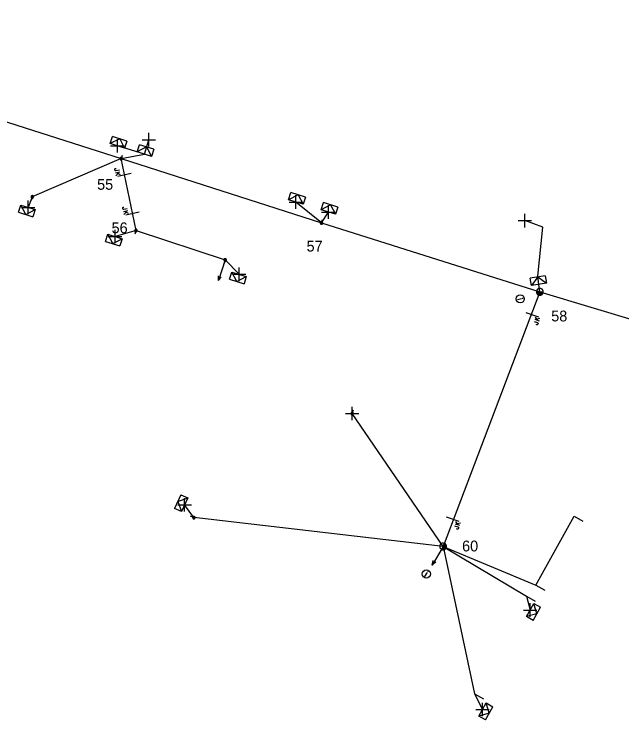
# Model space of a CAD drawing. Extents: x -540247 to -537390, y -1183887 to -1180355.
# Drawn here: x -537663.5 to -537607.2, y -1180540.3 to -1180475 of the extents above; entities that cross this region are included whole.
import ezdxf

# ---------------------------------------------------------------- set-up
doc = ezdxf.new("R2010")
doc.units = 0
for name, color, linetype in [('Vrstva 1', 7, 'Continuous'), ('Vrstva 10', 7, 'Continuous'), ('Vrstva 13', 7, 'Continuous'), ('Vrstva 14', 7, 'Continuous'), ('Vrstva 15', 7, 'Continuous'), ('Vrstva 18', 7, 'Continuous'), ('Vrstva 2', 7, 'Continuous'), ('Vrstva 31', 7, 'Continuous'), ('Vrstva 34', 7, 'Continuous'), ('Vrstva 36', 7, 'Continuous'), ('Vrstva 4', 7, 'Continuous'), ('Vrstva 50', 7, 'Continuous'), ('Vrstva 52', 7, 'Continuous'), ('Vrstva 54', 7, 'Continuous'), ('Vrstva 8', 7, 'Continuous'), ('Vrstva 9', 7, 'Continuous')]:
    doc.layers.add(name, color=color, linetype=linetype)

# ---------------------------------------------------------------- blocks, each defined once
blk = doc.blocks.new('NN440')
at = {"layer": 'Vrstva 2'}
for points in [[(0.63, 0), (0.63, 0.06), (0.62, 0.13), (0.6, 0.19), (0.58, 0.25), (0.55, 0.31), (0.51, 0.37), (0.47, 0.42), (0.42, 0.46), (0.37, 0.51), (0.32, 0.54), (0.26, 0.57), (0.2, 0.59), (0.13, 0.61), (0.07, 0.62), (0, 0.63), (-0.06, 0.62), (-0.13, 0.61), (-0.19, 0.59), (-0.26, 0.57), (-0.31, 0.54), (-0.37, 0.51), (-0.42, 0.46), (-0.47, 0.42), (-0.51, 0.37), (-0.54, 0.31), (-0.57, 0.25), (-0.6, 0.19), (-0.62, 0.13), (-0.63, 0.06), (-0.63, 0), (-0.63, -0.07), (-0.62, -0.14), (-0.6, -0.2), (-0.57, -0.26), (-0.54, -0.32), (-0.51, -0.37), (-0.47, -0.43), (-0.42, -0.47), (-0.37, -0.51), (-0.31, -0.55), (-0.26, -0.58), (-0.19, -0.6), (-0.13, -0.62), (-0.06, -0.63), (0, -0.63), (0.07, -0.63), (0.13, -0.62), (0.2, -0.6), (0.26, -0.58), (0.32, -0.55), (0.37, -0.51), (0.42, -0.47), (0.47, -0.43), (0.51, -0.37), (0.55, -0.32), (0.58, -0.26), (0.6, -0.2), (0.62, -0.14), (0.63, -0.07), (0.63, 0)], [(-0.63, 0), (0.63, 0)], [(-0.6, -0.18), (0.57, -0.18)], [(-0.51, -0.32), (0.5, -0.32)], [(-0.37, -0.47), (0.35, -0.47)]]:
    blk.add_lwpolyline(points, dxfattribs=at)
blk = doc.blocks.new('NN560')
at = {"layer": 'Vrstva 2'}
for points in [[(1.999, -0.001), (1.59, 0.141)], [(0, -0.001), (1.999, -0.001)], [(1.999, -0.001), (1.59, -0.134)]]:
    blk.add_lwpolyline(points, dxfattribs=at)
blk = doc.blocks.new('NN840')
at = {"layer": 'Vrstva 15'}
for points in [[(0.003, 0.619), (0.003, -0.631)], [(-0.538, -0.385), (-0.538, -0.71)], [(-0.332, -0.385), (-0.332, -0.798)], [(-0.332, -0.641), (-0.125, -0.385)], [(-0.263, -0.557), (-0.091, -0.798)], [(-0.745, -0.71), (-0.745, -0.66)], [(-0.73, -0.764), (-0.745, -0.71)], [(-0.657, -0.798), (-0.73, -0.764)], [(-0.627, -0.798), (-0.657, -0.798)], [(-0.558, -0.764), (-0.627, -0.798)], [(-0.538, -0.71), (-0.558, -0.764)]]:
    blk.add_lwpolyline(points, dxfattribs=at)
blk = doc.blocks.new('NN770')
at = {"layer": 'Vrstva 10'}
for p, q in [((0.002, 0.187), (0.002, 0.263)), ((0.002, -0.276), (0.002, 0.111))]:
    blk.add_line(p, q, dxfattribs=at)
blk.add_circle((0, -0.008), 0.375, dxfattribs=at)
blk = doc.blocks.new('NN800')
at = {"layer": 'Vrstva 1'}
for points in [[(-0.442, 0.442), (0.442, -0.442)], [(-0.442, -0.442), (0.442, 0.442)]]:
    blk.add_lwpolyline(points, dxfattribs=at)
blk = doc.blocks.new('NN630')
at = {"layer": 'Vrstva 9'}
for points in [[(-0.003, -0.7), (-0.703, 0)], [(-0.703, -0.7), (-0.703, 0), (0.697, 0), (0.697, -0.7)], [(-0.003, -0.7), (0.697, 0)], [(-0.703, -0.7), (0.697, -0.7)]]:
    blk.add_lwpolyline(points, dxfattribs=at)
blk = doc.blocks.new('NN500')
at = {"layer": 'Vrstva 2'}
for points in [[(0, -0.24), (0.02, -0.23), (0.05, -0.23), (0.07, -0.22), (0.09, -0.22), (0.12, -0.2), (0.14, -0.19), (0.16, -0.18), (0.17, -0.16), (0.19, -0.14), (0.2, -0.12), (0.21, -0.1), (0.22, -0.07), (0.23, -0.05), (0.23, -0.02), (0.23, 0), (0.23, 0.02), (0.23, 0.05), (0.22, 0.07), (0.21, 0.1), (0.2, 0.12), (0.19, 0.14), (0.17, 0.16), (0.16, 0.17), (0.14, 0.19), (0.12, 0.2), (0.09, 0.21), (0.07, 0.22), (0.05, 0.23), (0.02, 0.23), (0, 0.23), (-0.03, 0.23), (-0.05, 0.23), (-0.07, 0.22), (-0.1, 0.21), (-0.12, 0.2), (-0.14, 0.19), (-0.16, 0.17), (-0.18, 0.16), (-0.19, 0.14), (-0.2, 0.12), (-0.22, 0.1), (-0.22, 0.07), (-0.23, 0.05), (-0.23, 0.02), (-0.24, 0), (-0.23, -0.02), (-0.23, -0.05), (-0.22, -0.07), (-0.22, -0.1), (-0.2, -0.12), (-0.19, -0.14), (-0.18, -0.16), (-0.16, -0.18), (-0.14, -0.19), (-0.12, -0.2), (-0.1, -0.22), (-0.07, -0.22), (-0.05, -0.23), (-0.03, -0.23), (0, -0.24)], [(0, -0.24), (0.02, -0.23), (0.05, -0.23), (0.07, -0.22), (0.09, -0.22), (0.12, -0.2), (0.14, -0.19), (0.16, -0.18), (0.17, -0.16), (0.19, -0.14), (0.2, -0.12), (0.21, -0.1), (0.22, -0.07), (0.23, -0.05), (0.23, -0.02), (0.23, 0), (0.23, 0.02), (0.23, 0.05), (0.22, 0.07), (0.21, 0.1), (0.2, 0.12), (0.19, 0.14), (0.17, 0.16), (0.16, 0.17), (0.14, 0.19), (0.12, 0.2), (0.09, 0.21), (0.07, 0.22), (0.05, 0.23), (0.02, 0.23), (0, 0.23), (-0.03, 0.23), (-0.05, 0.23), (-0.07, 0.22), (-0.1, 0.21), (-0.12, 0.2), (-0.14, 0.19), (-0.16, 0.17), (-0.18, 0.16), (-0.19, 0.14), (-0.2, 0.12), (-0.22, 0.1), (-0.22, 0.07), (-0.23, 0.05), (-0.23, 0.02), (-0.24, 0), (-0.23, -0.02), (-0.23, -0.05), (-0.22, -0.07), (-0.22, -0.1), (-0.2, -0.12), (-0.19, -0.14), (-0.18, -0.16), (-0.16, -0.18), (-0.14, -0.19), (-0.12, -0.2), (-0.1, -0.22), (-0.07, -0.22), (-0.05, -0.23), (-0.03, -0.23), (0, -0.24)], [(0, -0.21), (0.02, -0.2), (0.04, -0.2), (0.06, -0.2), (0.08, -0.19), (0.1, -0.18), (0.12, -0.17), (0.14, -0.15), (0.15, -0.14), (0.16, -0.12), (0.18, -0.1), (0.19, -0.08), (0.19, -0.06), (0.2, -0.04), (0.2, -0.02), (0.2, 0), (0.2, 0.02), (0.2, 0.04), (0.19, 0.06), (0.19, 0.08), (0.18, 0.1), (0.16, 0.12), (0.15, 0.14), (0.14, 0.15), (0.12, 0.17), (0.1, 0.18), (0.08, 0.19), (0.06, 0.19), (0.04, 0.2), (0.02, 0.2), (0, 0.2), (-0.02, 0.2), (-0.04, 0.2), (-0.06, 0.19), (-0.08, 0.19), (-0.1, 0.18), (-0.12, 0.17), (-0.14, 0.15), (-0.15, 0.14), (-0.17, 0.12), (-0.18, 0.1), (-0.19, 0.08), (-0.2, 0.06), (-0.2, 0.04), (-0.21, 0.02), (-0.21, 0), (-0.21, -0.02), (-0.2, -0.04), (-0.2, -0.06), (-0.19, -0.08), (-0.18, -0.1), (-0.17, -0.12), (-0.15, -0.14), (-0.14, -0.15), (-0.12, -0.17), (-0.1, -0.18), (-0.08, -0.19), (-0.06, -0.2), (-0.04, -0.2), (-0.02, -0.2), (0, -0.21)], [(0, -0.18), (0.02, -0.18), (0.04, -0.17), (0.05, -0.17), (0.07, -0.16), (0.09, -0.15), (0.1, -0.14), (0.12, -0.13), (0.13, -0.12), (0.14, -0.1), (0.15, -0.09), (0.16, -0.07), (0.17, -0.05), (0.17, -0.04), (0.17, -0.02), (0.17, 0), (0.17, 0.02), (0.17, 0.04), (0.17, 0.05), (0.16, 0.07), (0.15, 0.09), (0.14, 0.1), (0.13, 0.12), (0.12, 0.13), (0.1, 0.14), (0.09, 0.15), (0.07, 0.16), (0.05, 0.17), (0.04, 0.17), (0.02, 0.17), (0, 0.18), (-0.02, 0.17), (-0.04, 0.17), (-0.06, 0.17), (-0.07, 0.16), (-0.09, 0.15), (-0.1, 0.14), (-0.12, 0.13), (-0.13, 0.12), (-0.14, 0.1), (-0.15, 0.09), (-0.16, 0.07), (-0.17, 0.05), (-0.17, 0.04), (-0.18, 0.02), (-0.18, 0), (-0.18, -0.02), (-0.17, -0.04), (-0.17, -0.05), (-0.16, -0.07), (-0.15, -0.09), (-0.14, -0.1), (-0.13, -0.12), (-0.12, -0.13), (-0.1, -0.14), (-0.09, -0.15), (-0.07, -0.16), (-0.06, -0.17), (-0.04, -0.17), (-0.02, -0.18), (0, -0.18)], [(0, -0.15), (0.01, -0.15), (0.03, -0.14), (0.04, -0.14), (0.06, -0.13), (0.07, -0.13), (0.08, -0.12), (0.1, -0.11), (0.11, -0.1), (0.12, -0.09), (0.13, -0.07), (0.13, -0.06), (0.14, -0.05), (0.14, -0.03), (0.14, -0.02), (0.14, 0), (0.14, 0.01), (0.14, 0.03), (0.14, 0.04), (0.13, 0.06), (0.13, 0.07), (0.12, 0.09), (0.11, 0.1), (0.1, 0.11), (0.08, 0.12), (0.07, 0.13), (0.06, 0.13), (0.04, 0.14), (0.03, 0.14), (0.01, 0.14), (0, 0.15), (-0.02, 0.14), (-0.03, 0.14), (-0.05, 0.14), (-0.06, 0.13), (-0.07, 0.13), (-0.09, 0.12), (-0.1, 0.11), (-0.11, 0.1), (-0.12, 0.09), (-0.13, 0.07), (-0.13, 0.06), (-0.14, 0.04), (-0.14, 0.03), (-0.15, 0.01), (-0.15, 0), (-0.15, -0.02), (-0.14, -0.03), (-0.14, -0.05), (-0.13, -0.06), (-0.13, -0.07), (-0.12, -0.09), (-0.11, -0.1), (-0.1, -0.11), (-0.09, -0.12), (-0.07, -0.13), (-0.06, -0.13), (-0.05, -0.14), (-0.03, -0.14), (-0.02, -0.15), (0, -0.15)], [(0, -0.12), (0.01, -0.12), (0.02, -0.11), (0.03, -0.11), (0.05, -0.11), (0.06, -0.1), (0.07, -0.09), (0.08, -0.09), (0.09, -0.08), (0.09, -0.07), (0.1, -0.06), (0.11, -0.05), (0.11, -0.04), (0.11, -0.02), (0.11, -0.01), (0.12, 0), (0.11, 0.01), (0.11, 0.02), (0.11, 0.04), (0.11, 0.05), (0.1, 0.06), (0.09, 0.07), (0.09, 0.08), (0.08, 0.09), (0.07, 0.09), (0.06, 0.1), (0.05, 0.11), (0.03, 0.11), (0.02, 0.11), (0.01, 0.12), (0, 0.12), (-0.01, 0.12), (-0.03, 0.11), (-0.04, 0.11), (-0.05, 0.11), (-0.06, 0.1), (-0.07, 0.09), (-0.08, 0.09), (-0.09, 0.08), (-0.1, 0.07), (-0.1, 0.06), (-0.11, 0.05), (-0.11, 0.04), (-0.12, 0.02), (-0.12, 0.01), (-0.12, 0), (-0.12, -0.01), (-0.12, -0.02), (-0.11, -0.04), (-0.11, -0.05), (-0.1, -0.06), (-0.1, -0.07), (-0.09, -0.08), (-0.08, -0.09), (-0.07, -0.09), (-0.06, -0.1), (-0.05, -0.11), (-0.04, -0.11), (-0.03, -0.11), (-0.01, -0.12), (0, -0.12)], [(0, -0.09), (0.01, -0.09), (0.02, -0.09), (0.03, -0.08), (0.03, -0.08), (0.04, -0.08), (0.05, -0.07), (0.06, -0.07), (0.06, -0.06), (0.07, -0.05), (0.07, -0.04), (0.08, -0.04), (0.08, -0.03), (0.08, -0.02), (0.09, -0.01), (0.09, 0), (0.09, 0.01), (0.08, 0.02), (0.08, 0.03), (0.08, 0.03), (0.07, 0.04), (0.07, 0.05), (0.06, 0.06), (0.06, 0.06), (0.05, 0.07), (0.04, 0.07), (0.03, 0.08), (0.03, 0.08), (0.02, 0.08), (0.01, 0.09), (0, 0.09), (-0.01, 0.09), (-0.02, 0.08), (-0.03, 0.08), (-0.04, 0.08), (-0.04, 0.07), (-0.05, 0.07), (-0.06, 0.06), (-0.07, 0.06), (-0.07, 0.05), (-0.08, 0.04), (-0.08, 0.03), (-0.08, 0.03), (-0.09, 0.02), (-0.09, 0.01), (-0.09, 0), (-0.09, -0.01), (-0.09, -0.02), (-0.08, -0.03), (-0.08, -0.04), (-0.08, -0.04), (-0.07, -0.05), (-0.07, -0.06), (-0.06, -0.07), (-0.05, -0.07), (-0.04, -0.08), (-0.04, -0.08), (-0.03, -0.08), (-0.02, -0.09), (-0.01, -0.09), (0, -0.09)], [(0, -0.06), (0, -0.06), (0.01, -0.06), (0.02, -0.05), (0.02, -0.05), (0.03, -0.05), (0.03, -0.05), (0.04, -0.04), (0.04, -0.04), (0.05, -0.03), (0.05, -0.03), (0.05, -0.02), (0.05, -0.02), (0.05, -0.01), (0.06, -0.01), (0.06, 0), (0.06, 0.01), (0.05, 0.01), (0.05, 0.02), (0.05, 0.02), (0.05, 0.03), (0.05, 0.03), (0.04, 0.04), (0.04, 0.04), (0.03, 0.05), (0.03, 0.05), (0.02, 0.05), (0.02, 0.05), (0.01, 0.06), (0, 0.06), (0, 0.06), (-0.01, 0.06), (-0.01, 0.06), (-0.02, 0.05), (-0.02, 0.05), (-0.03, 0.05), (-0.03, 0.05), (-0.04, 0.04), (-0.04, 0.04), (-0.05, 0.03), (-0.05, 0.03), (-0.05, 0.02), (-0.06, 0.02), (-0.06, 0.01), (-0.06, 0.01), (-0.06, 0), (-0.06, -0.01), (-0.06, -0.01), (-0.06, -0.02), (-0.05, -0.02), (-0.05, -0.03), (-0.05, -0.03), (-0.04, -0.04), (-0.04, -0.04), (-0.03, -0.05), (-0.03, -0.05), (-0.02, -0.05), (-0.02, -0.05), (-0.01, -0.06), (-0.01, -0.06), (0, -0.06)], [(0, -0.03), (0, -0.03), (0, -0.03), (0.01, -0.03), (0.01, -0.03), (0.01, -0.02), (0.02, -0.02), (0.02, -0.02), (0.02, -0.02), (0.02, -0.02), (0.02, -0.01), (0.02, -0.01), (0.03, -0.01), (0.03, -0.01), (0.03, 0), (0.03, 0), (0.03, 0), (0.03, 0.01), (0.03, 0.01), (0.02, 0.01), (0.02, 0.01), (0.02, 0.02), (0.02, 0.02), (0.02, 0.02), (0.02, 0.02), (0.01, 0.02), (0.01, 0.02), (0.01, 0.03), (0, 0.03), (0, 0.03), (0, 0.03), (0, 0.03), (-0.01, 0.03), (-0.01, 0.03), (-0.01, 0.02), (-0.02, 0.02), (-0.02, 0.02), (-0.02, 0.02), (-0.02, 0.02), (-0.02, 0.02), (-0.03, 0.01), (-0.03, 0.01), (-0.03, 0.01), (-0.03, 0.01), (-0.03, 0), (-0.03, 0), (-0.03, 0), (-0.03, -0.01), (-0.03, -0.01), (-0.03, -0.01), (-0.03, -0.01), (-0.02, -0.02), (-0.02, -0.02), (-0.02, -0.02), (-0.02, -0.02), (-0.02, -0.02), (-0.01, -0.03), (-0.01, -0.03), (-0.01, -0.03), (0, -0.03), (0, -0.03)], [(0.23, 0), (0.7, 0)]]:
    blk.add_lwpolyline(points, dxfattribs=at)
blk = doc.blocks.new('NN510')
at = {"layer": 'Vrstva 2'}
blk.add_lwpolyline([(0.001, 0.002), (0.001, 0.939)], dxfattribs=at)

msp = doc.modelspace()

# ---------------------------------------------------------------- linework, layer by layer
at = {"layer": 'Vrstva 4'}
msp.add_lwpolyline([(-537652.173, -1180495.016), (-537643.924, -1180497.74), (-537642.633, -1180499.066)], dxfattribs=at)
at = {"layer": 'Vrstva 50'}
for points in [[(-537694.091, -1180474.974), (-537666.22, -1180484.298), (-537653.537, -1180488.361)], [(-537653.537, -1180488.361), (-537651.403, -1180487.946)], [(-537653.537, -1180488.361), (-537635.007, -1180494.316), (-537614.792, -1180500.692)], [(-537614.792, -1180500.692), (-537595.92, -1180506.36)]]:
    msp.add_lwpolyline(points, dxfattribs=at)
at = {"layer": 'Vrstva 52'}
for points in [[(-537652.173, -1180495.016), (-537653.537, -1180488.361)], [(-537614.792, -1180500.692), (-537614.882, -1180500.012), (-537614.977, -1180499.247), (-537614.51, -1180494.707), (-537616.189, -1180494.101)], [(-537614.792, -1180500.692), (-537623.75, -1180524.27)]]:
    msp.add_lwpolyline(points, dxfattribs=at)
at = {"layer": 'Vrstva 54'}
for points in [[(-537651.403, -1180487.946), (-537650.981, -1180486.604)], [(-537651.403, -1180487.946), (-537653.899, -1180487.179)], [(-537653.537, -1180488.361), (-537661.775, -1180491.901), (-537662.162, -1180492.869)], [(-537635.007, -1180494.316), (-537637.382, -1180492.377)], [(-537635.007, -1180494.316), (-537634.369, -1180493.305)], [(-537652.173, -1180495.016), (-537654.116, -1180495.567)], [(-537623.75, -1180524.27), (-537632.166, -1180511.964)], [(-537623.75, -1180524.27), (-537646.819, -1180521.603), (-537647.673, -1180520.414)], [(-537623.75, -1180524.27), (-537615.153, -1180527.849), (-537611.624, -1180521.473)], [(-537623.75, -1180524.27), (-537620.835, -1180537.922), (-537620.106, -1180539.382)]]:
    msp.add_lwpolyline(points, dxfattribs=at)
at = {"layer": 'Vrstva 8'}
msp.add_lwpolyline([(-537623.75, -1180524.27), (-537616.03, -1180528.887), (-537615.685, -1180530.164)], dxfattribs=at)

# ---------------------------------------------------------------- block references
at = {"layer": 'Vrstva 13'}
for name, p, xscale, yscale, rotation in [('NN500', (-537653.537, -1180488.361), 0.5, 0.5, 72.14200004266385), ('NN500', (-537661.775, -1180491.901), 0.5, 0.5, -107.78899997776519), ('NN500', (-537635.007, -1180494.316), 0.5, 0.5, 72.58399999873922), ('NN500', (-537652.173, -1180495.016), 0.49999999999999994, 0.5, -107.88299999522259), ('NN500', (-537643.924, -1180497.74), 0.5, 0.49999999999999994, -107.08100003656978), ('NN500', (-537632.166, -1180511.964), 0.5, 0.5, 71.9319999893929), ('NN500', (-537646.819, -1180521.603), 0.5, 0.5, 155.21199998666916), ('NN440', (-537623.75, -1180524.27), 0.5, 0.5, 66.15376666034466)]:
    msp.add_blockref(name, p, dxfattribs=dict(at, xscale=xscale, yscale=yscale, rotation=rotation))
for name, p, rotation in [('NN560', (-537643.924, -1180497.74), -108.25003885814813), ('NN510', (-537611.624, -1180521.472), -119.29900838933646), ('NN560', (-537623.75, -1180524.27), -120.23498889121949), ('NN510', (-537615.153, -1180527.848), -119.29802498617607), ('NN510', (-537616.03, -1180528.886), -119.37576672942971), ('NN510', (-537620.835, -1180537.921), -119.26119724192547)]:
    msp.add_blockref(name, p, dxfattribs=dict(at, rotation=rotation))
at = {"layer": 'Vrstva 13', "xscale": 0.5, "yscale": 0.5}
msp.add_blockref('NN440', (-537614.792, -1180500.692), dxfattribs=at)
at = {"layer": 'Vrstva 18'}
for p, rotation in [((-537653.228, -1180489.871), -78.41714723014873), ((-537652.494, -1180493.452), -78.41714716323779), ((-537615.515, -1180502.801), 71.07846664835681), ((-537622.879, -1180521.728), 71.07846664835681)]:
    msp.add_blockref('NN840', p, dxfattribs=dict(at, rotation=rotation))
at = {"layer": 'Vrstva 31'}
for p, rotation in [((-537653.899, -1180487.179), 162.14193608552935), ((-537651.403, -1180487.946), 162.45832213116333), ((-537637.382, -1180492.377), 162.45832224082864), ((-537634.369, -1180493.305), 162.5844417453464), ((-537662.162, -1180492.869), -17.78913048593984), ((-537654.116, -1180495.567), -17.883041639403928), ((-537642.633, -1180499.066), -17.080766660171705), ((-537614.882, -1180500.012), -171.25383878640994), ((-537647.673, -1180520.414), -114.78776674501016), ((-537615.685, -1180530.164), 60.73880281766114), ((-537620.106, -1180539.382), 60.900474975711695)]:
    msp.add_blockref('NN630', p, dxfattribs=dict(at, rotation=rotation))
at = {"layer": 'Vrstva 34'}
for p, rotation in [((-537650.981, -1180486.604), 45), ((-537653.899, -1180487.178), 45), ((-537637.382, -1180492.377), 45), ((-537662.162, -1180492.869), 45.00000009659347), ((-537634.369, -1180493.305), 44.99999995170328), ((-537616.189, -1180494.101), 45), ((-537654.116, -1180495.567), 45), ((-537642.633, -1180499.066), 45), ((-537632.166, -1180511.964), 45), ((-537647.673, -1180520.414), 44.99999995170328), ((-537615.685, -1180530.164), 45), ((-537620.106, -1180539.382), 45)]:
    msp.add_blockref('NN800', p, dxfattribs=dict(at, rotation=rotation))
at = {"layer": 'Vrstva 36'}
for p, rotation in [((-537616.603, -1180501.343), -74.89890281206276), ((-537625.298, -1180526.817), -32.949213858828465)]:
    msp.add_blockref('NN770', p, dxfattribs=dict(at, rotation=rotation))

# ---------------------------------------------------------------- texts
at = {"layer": 'Vrstva 14'}
for s, p in [('55', (-537655.776, -1180491.244)), ('56', (-537654.437, -1180495.267)), ('57', (-537636.386, -1180496.963)), ('58', (-537613.742, -1180503.434)), ('60', (-537621.991, -1180524.734))]:
    msp.add_text(s, height=1, dxfattribs=at).set_placement(p)

doc.saveas('drawing.dxf')
